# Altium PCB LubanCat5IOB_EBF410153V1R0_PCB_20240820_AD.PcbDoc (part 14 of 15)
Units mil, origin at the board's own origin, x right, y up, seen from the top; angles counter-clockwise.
Board outline 6811.02 x 4055.12 mil, 6 copper layers (TOP, GND02, ART03, ART04, PWR05, BOTTOM), stack 59.279 mil thick; 981 components, 783 nets, 3627 pads, 2669 vias.
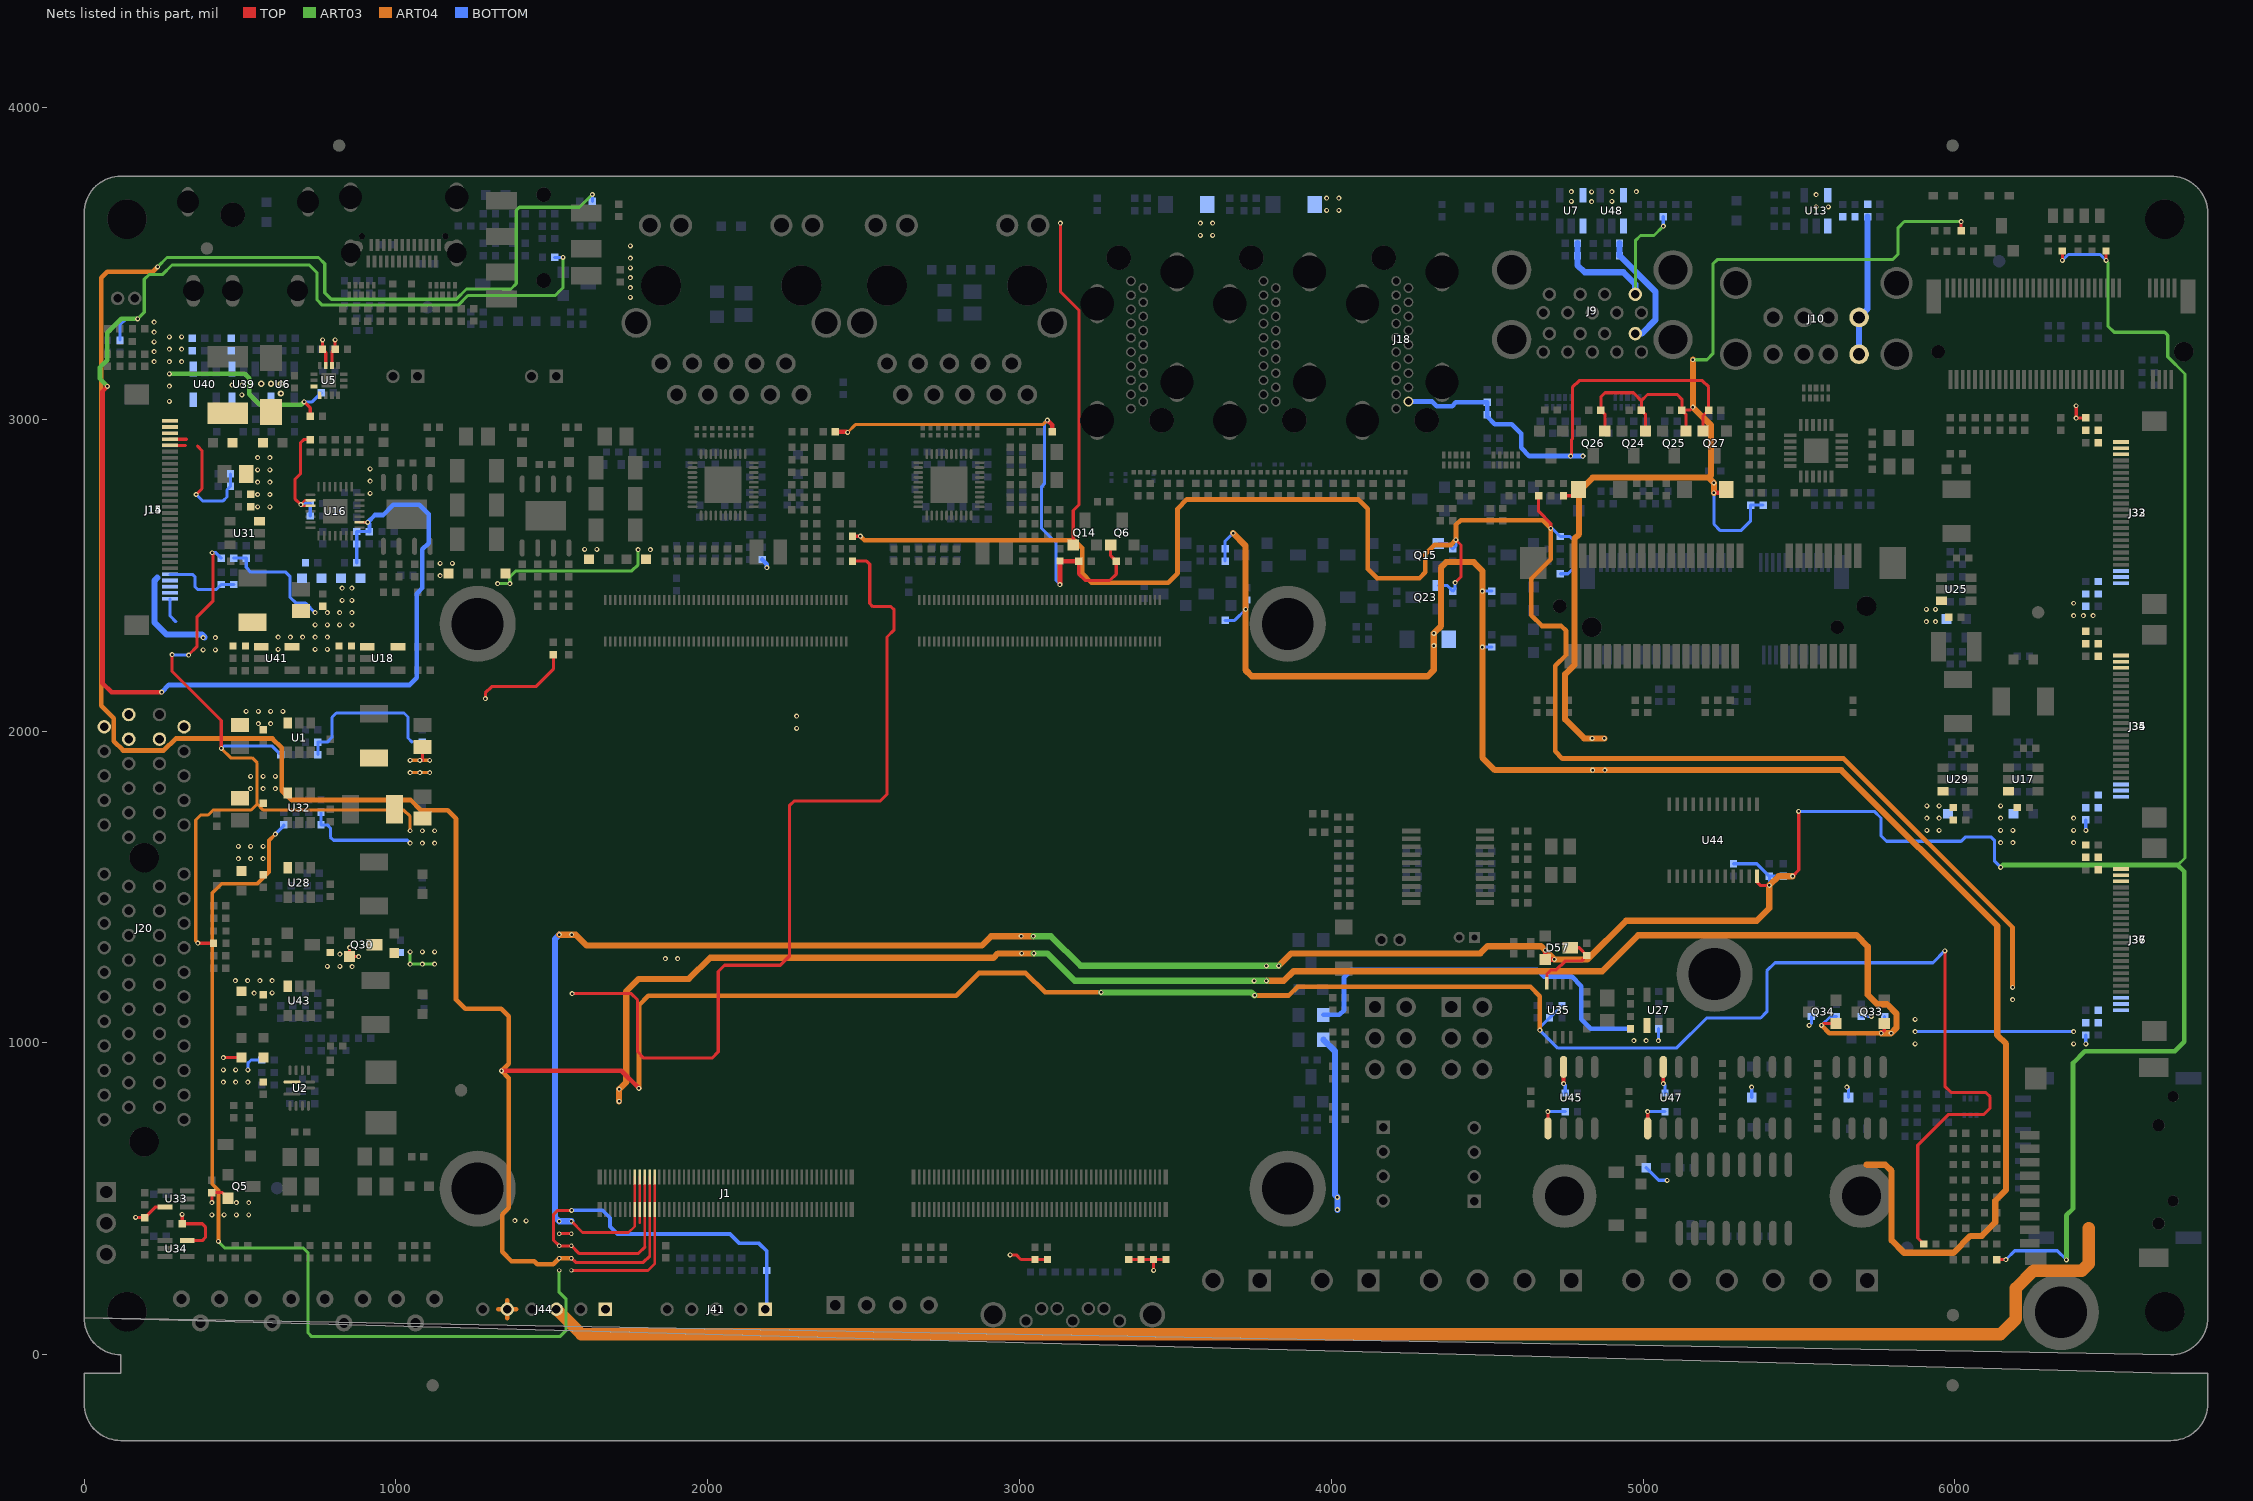
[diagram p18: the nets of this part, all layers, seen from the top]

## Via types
v1: diameter 16, hole 8, TOP to BOTTOM, 2357 vias
v2: diameter 14, hole 8, TOP to BOTTOM, 308 vias
v3: diameter 20, hole 10, TOP to BOTTOM, 4 vias

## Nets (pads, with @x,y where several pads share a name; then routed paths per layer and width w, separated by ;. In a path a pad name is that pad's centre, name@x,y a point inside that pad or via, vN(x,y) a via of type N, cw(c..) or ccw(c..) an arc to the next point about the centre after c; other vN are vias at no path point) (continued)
VCC5V0_HDMI_RX: C155.1 D40.2 D45.2 J18.18 Q27.2 R193.1 R213.1 | length 1577.4
  TOP w10: R193.1@4745,2754.69 4773.39,2754.69 D40.2@4793.07,2774.37 ; v1(4768,2882.16) 4771,2885.16 4771,2934.74 4773.5,2937.24 4773.5,3102.55 4795,3124.05 5190.32,3124.05 5210.32,3104.05 R213.1@5210.32,3029.37 5192.5,3011.55 Q27.2@5192.5,2962.87
  BOTTOM w15: J18.18@4247.48,3056.98 4323.94,3056.98 4338.74,3042.18 4387.81,3042.18 4400,3054.37 D45.2@4500.32,3054.37 C155.1@4500.32,3014.37 4500.32,3009.05 4525,2984.37 4579,2984.37 4609,2954.37 4609,2908.37 4635.21,2882.16 v1(4768,2882.16) v1(4807.37,2882.16)
VCC5V0_USB20_HOST: C285.1 C286.1 J9.10 U48.1 | length 376
  BOTTOM w20: C285.1@4924.68,3564.37 C286.1@4924.68,3524.37 5040,3409.05 5040,3319.37 4995.5,3274.86 J9.10@4975.24,3274.86
VCC5V0_USB20_HUB: C92.1 C97.1 C100.1 C101.1 J10.1 J10.7 U13.1 | length 452.1
  BOTTOM w20: J10.1@5692.92,3208.66 J10.7@5692.92,3326.77 5720.32,3354.17 C92.1@5720.32,3649.37
VCC5V0_USB30_OTG: C90.1 C91.1 J9.1 R150.1 U7.1 | length 624.4
  ART03 w10: J9.1@4975.24,3400.86 4975.24,3572.61 4992,3589.37 5035,3589.37 v1(5065,3619.37)
  BOTTOM w10: v1(5065,3619.37) R150.1@5065,3649.69
  BOTTOM w20: C90.1@4789.68,3564.37 C91.1@4789.68,3524.37 4789.68,3494.37 4812.68,3471.37 4937,3471.37 4975.24,3433.13 J9.1@4975.24,3400.86
VCC5V0_USB_S0: C7.2 C8.1 C11.1 C72.1 C73.1 L2.2 R4.2 U5.12 U5.13 U6.5 U7.5 U13.5 U48.5 | length 838.5
  TOP w10: v1(764.68,3254.68) C72.1@764.68,3225 775.16,3214.52 U5.13@775.16,3172.64 ; U5.12@794.84,3172.64 794.84,3214.52 C73.1@805.32,3225 v1(805.32,3254.68) ; v1@1085,1906.37 C8.1@1085,1949.33
  ART04 w10: v1(1045.63,1867) v1(1077.12,1867) v1(1108.61,1867) ; v1(1045.63,1906.37) v1(1077.12,1906.37) v1(1108.61,1906.37)
  BOTTOM w10: R4.2@749.68,1924.37 C7.2@749.68,1964.37 750,1964.69 779.69,1964.69 795,1980 795,2044 809.14,2058.14 1025.86,2058.14 1039,2045 1039,1977.69 1052,1964.69
  other v1: 224.37,3185.37 224.37,3216.86 224.37,3248.35 224.37,3279.84 224.37,3311.33 1752,3391.04 1752,3422.53 1752,3454.02 1752,3485.51 1752,3517 1752,3556.37 5555.03,3680.97 5594.4,3680.97 4835,3697.88 4770,3698.74 4900,3698.74 5555.03,3720.34 4835,3729.37 4770,3730.23 4900,3730.23 4978.74,3730.23
  other v3: 631.09,3082.51 568.11,3114 599.6,3114 631.09,3114
VCC12V_PCIEX4: C197.1 C198.1 J20.A2 J20.A3 J20.B1 J20.B2 J20.B3 Q30.3 | length 119.7
  ART03 w10: v1@1044.52,1293 v1(1045.63,1291.89) v1(1045.63,1252.52) v1(1085,1252.52) v1(1124.37,1252.52)
  other v1: 1085,1291.89 1124.37,1291.89
VCC_1V8_S0: J1.21 J1.22 Q15.1 Q23.1 Q33.1 Q34.1 R172.1 R174.1 R175.1 R191.1 R210.1 R273.2 R329.1 R332.1 R381.2 | length 15301.2
  TOP w8: 1829.63,291 J1.22@1829.63,465.62 J1.21@1829.63,569.96
  TOP w10: v2(1563.09,270.1) 1808.73,270.1 1829.63,291 ; R381.2@2464.68,2625 v1(2490,2625) ; v1(4397,2476) 4416,2495 4416,2597 v1(4400,2613) ; R210.1@4665,2754.69 4665,2705 4704,2666 v1(4704,2650) ; v1(5572.37,1056) 5578.24,1061.87 Q34.1@5618.5,1061.87 ; v1(5764,1030.87) 5773.5,1040.37 Q33.1@5773.5,1061.87
  ART03 w10: v1(431,363) 431,362 451,342 703,342 718,327 718,70 730,58 1526,58 1546,78 1546,178 1523.72,200.28 v2(1523.72,270.1)
  ART03 w20: v1(3046,1287) 3089,1287 3177,1199 v1(3752.63,1199) v1(3792,1199)
  ART04 w12: v1(431,363) 431,527 411,547 411,1481 440,1510 555,1510 593.23,1548.23 593.23,1649.37 v1(613.23,1669.37)
  ART04 w15: v1(2490,2625) 2503,2612 3176,2612 3201,2587 3201,2506 3231,2476 3477,2476 3507,2506 3507,2713 3537,2743 4087,2743 4117,2713 4117,2520 4147,2490 4283,2490 4302,2509 4302,2567 4332,2597 4384,2597 v1(4400,2613) 4400,2661.37 4415,2676.37 4677.63,2676.37 v1(4704,2650) 4704,2551 4641,2488 4641,2372.21 4676.21,2337 4738,2337 4753,2322 4753,2244 4718,2209 4718,1935 4741,1912 5644,1912 6185,1371 v1(6185,1178) ; v1(5572.37,1056) 5597.5,1030.87 v1(5764,1030.87)
  ART04 w20: v1(1716,812) v1(1716,851.37) 1739,874.37 1739,1165 1779,1205 1940,1205 2008,1273 2917,1273 2931,1287 v1(3006.63,1287) v1(3046,1287) ; v1(3792,1199) 3848,1199 3879,1230 4869,1230 4984,1345 5685,1345 5721,1309 5721,1154 5751,1124 5783,1124 5813,1094 5813,1048.38 v1(5795.49,1030.87) v1(5764,1030.87)
  BOTTOM w10: v1(613.23,1669.37) 640.32,1696.46 R273.2@640.32,1699.37 ; Q23.1@4343.5,2466.87 4372.18,2466.87 R191.1@4390,2449.05 4397,2456.05 v1(4397,2476) ; Q15.1@4343.5,2601.87 4372.18,2601.87 R172.1@4390,2584.05 4400,2594.05 v1(4400,2613) ; v1(4704,2650) 4709.05,2650 R174.1@4735,2624.05 4765.32,2624.05 4780,2609.37 4780,2525.33 4759.36,2504.69 R175.1@4735,2504.69 ; v1(5572.37,1056) 5601.06,1084.69 R332.1@5620,1084.69 ; v1(5764,1030.87) 5775,1041.87 R329.1@5775,1084.69
  other v1: 6185,1138.63
VCC_1V8_S3: J1.19 J1.20 R3.1 R119.1 R276.1 R284.1 | length 13845.3
  TOP w8: 1813.88,316 J1.20@1813.88,465.62 J1.19@1813.88,569.96
  TOP w10: v2(1563.09,309.47) 1576.56,296 1793.88,296 1813.88,316 ; R284.1@5900.32,355 5881,374.32 5881,672 5979,770 6092,770 6113.14,791.14 6113.14,826.86 6099,841 5988,841 5968,861 v1(5968,1295)
  TOP w15: v1(1338.74,910.37) 1723.35,910.37 v1(1779.71,854)
  ART03 w10: v1(236,3489) 266,3519 752,3519 772,3499 772,3406 793,3385 1193.54,3385 1226.54,3418 1369,3418 1386,3435 1386,3670 1396,3680 1589,3680 v1(1630,3721)
  ART03 w20: v1(3262,1162) 3744,1162 v1(3754,1152)
  ART04 w15: v1(236,3489) 220,3473 74,3473 55,3454 55,2081 95,2041 95,1968 125,1938 256,1938 294,1976 604,1976 634,1946 634,1809 664,1779 1047,1779 1080,1746 1166,1746 1193,1719 1193,1139 1223,1109 1338.13,1109 1362,1085.13 1362,933.63 v1(1338.74,910.37) 1362,887.11 1362,471 1340.79,449.79 1340.79,330 1370.79,300 1443.56,300 1453.59,289.97 1504.22,289.97 v2(1523.72,309.47) v2(1563.09,309.47) ; v1(1779.71,854) 1779.71,1121 1809.72,1151 2797,1151 2870,1224 3020,1224 3082,1162 v1(3262,1162) ; v1(3754,1152) 3864,1152 3892,1180 4639.05,1180 4669.05,1150 v1(4669.05,1040.95)
  BOTTOM w10: R119.1@1630,3699.05 v1(1630,3721) ; R3.1@4740,1119.68 4700.64,1080.32 R276.1@4700,1080.32 4669.05,1049.37 v1(4669.05,1040.95) 4727,983 5107,983 5204,1080 5377,1080 5397,1100 5397,1231 5423,1257 5930,1257 v1(5968,1295)
VCC_3V3_S0: C93.1 C216.1 C230.1 C231.1 C232.2 C313.1 D46.2 D49.2 J44.5 L21.2 L22.1 L23.1 L24.2 Q6.1 Q24.1 Q25.1 Q26.1 R6.2 R65.2 R100.1 R128.1 R151.1 R153.1 R154.1 R157.1 R158.1 R170.1 R178.1 R179.1 R196.1 R198.1 R199.1 R246.2 R272.2 R328.1 R330.1 R331.1 R356.1 R357.1 R358.1 R359.1 R360.1 R361.1 R363.2 R364.2 R382.2 R383.2 U45.5 U47.5 | length 15595
  TOP w10: v1(282,2245) 282,2192 440,2034 v1(440,1944.37) ; v1(335,2244) 362.57,2271.57 362.57,2366.57 414,2418 414,2569 v1(411,2572) ; v1(365.32,1319.69) R328.1@415,1319.69 ; v1(2970,320) 2990,320 3004.68,305.32 R360.1@3050,305.32 R361.1@3090,305.32 ; R170.1@3190.32,2545 3190.32,2503.32 3210.32,2483.32 3290.32,2483.32 3310.32,2503.32 R151.1@3310.32,2545 3292.5,2562.82 Q6.1@3292.5,2596.5 ; R358.1@3350,305.32 R359.1@3390,305.32 R356.1@3430,305.32 ; v1(3430,270) R356.1@3430,305.32 ; R357.1@3470,305.32 R356.1@3430,305.32 ; U45.5@4695,725.95 v1(4695,779.37) ; Q26.1@4877.5,2962.87 4877.5,3016.55 R199.1@4864.68,3029.37 4864.68,3071.68 4878,3085 4969.37,3085 4994.68,3059.69 ; Q24.1@5007.5,2962.87 5007.5,3016.55 R196.1@4994.68,3029.37 4994.68,3059.69 ; U47.5@5015,725.95 v1(5015,779.37) ; Q25.1@5137.5,2962.87 5137.5,3016.55 R198.1@5124.68,3029.37 ; v1(5160,3038.74) 5150.63,3029.37 R198.1@5124.68,3029.37 ; R128.1@6020.32,3604.37 v1(6020.32,3634.37) ; 4994.68,3059.69 5014.36,3079.37 5110,3079.37 5124.68,3064.69 R198.1@5124.68,3029.37
  TOP w15: R383.2@2409.68,2960 2446.41,2960 v1(2448.61,2957.8) ; v1(3089.28,2997.17) 3104.68,2981.77 R364.2@3104.68,2960 ; v1(3130,2470) R363.2@3130,2545.32 3130.32,2545 R170.1@3190.32,2545 ; v1(5227.37,2764.37) 5256.93,2764.37 D46.2@5266.93,2774.37
  ART03 w10: v1(5160,3191) 5205,3191 5224,3210 5224,3498 5238,3512 5800,3512 5818,3530 5818,3614.37 5838,3634.37 v1(6020.32,3634.37)
  ART04 w10: v1(365.32,1319.69) 358,1327.01 358,1715 374,1731 398.01,1731 414.01,1747 535.63,1747 555,1766.37 ; v1(440,1944.37) 470.37,1914 538.9,1914 555,1897.9 555,1766.37 ; v1(1045.63,1680.37) 1045.63,1726.37 1025.63,1746.37 575,1746.37 555,1766.37 ; v1(2448.61,2957.8) 2473.81,2983 3075.11,2983 v1(3089.28,2997.17)
  ART04 w15: J44.5@1328.63,145.66 J44.5@1357.28,145.66 ; J44.5@1357.28,117.01 J44.5@1357.28,145.66 ; J44.5@1357.28,174.32 J44.5@1357.28,145.66 ; J44.5@1385.94,145.66 J44.5@1357.28,145.66
  ART04 w20: v1(3685,2635) 3725,2595 v1(3725,2390) 3725,2196 3745,2176 4309,2176 4329,2196 v1(4329,2274.37) v1(4329,2313.74) 4352,2336.74 4352,2525 4369,2542 4456.72,2542 4485,2513.72 v1(4485,2449.05) v1(4485,2269.69) 4485,1915 4525,1875 v1(4838,1875) v1(4877.37,1875) 5636,1875 6136,1375 6136,1025 6164.28,996.72 6164.28,528.28 6130,494 6130,424 6087,381 6050,381 5996,327 5837,327 5797,367 5797,589 5777,609 5717,609 ; v1(4876.03,1976.62) v1(4836.66,1976.62) 4811.38,1976.62 4750,2038 4750,2182 4780,2212 4780,2617 4795,2632 4795,2769 4839,2813 5210.23,2813 ; v1(5160,3191) v1(5160,3038.74) 5218,2980.74 5218,2820.77 5210.23,2813 ; v1(5227.37,2764.37) v1(5227.37,2795.86) 5210.23,2813
  BOTTOM w10: v1(282,2245) 283,2244 v1(335,2244) ; v1(411,2572) 422.69,2572 R65.2@440,2554.69 ; v1(440,1944.37) 448.37,1952.74 601.95,1952.74 R6.2@630.32,1924.37 ; C232.2@759.68,1739.37 R272.2@759.68,1699.37 780,1699.37 790,1689.37 790,1660 800,1650 1036.63,1650 v1(1045.63,1641) ; v1(3089.28,2997.17) 3080,2987.89 3080,2793 3071,2784 3071,2650 3117,2604 3117,2483 v1(3130,2470) ; R157.1@3659.68,2355 3690,2355 v1(3725,2390) 3730,2395 R158.1@3730,2420.32 ; R154.1@3659.68,2545 R153.1@3659.68,2585 3659.68,2609.68 v1(3685,2635) ; v1(4485,2269.69) R179.1@4515,2269.69 ; v1(4485,2449.05) R178.1@4515,2449.05 ; v1(4695,779.37) C216.1@4750.32,779.37 ; v1(5015,779.37) C313.1@5070.32,779.37 ; v1(5049.43,1007.21) 5050,1007.78 R246.2@5050,1045.32 ; v1(5227.37,2764.37) 5227.37,2663.63 5248,2643 5313.63,2643 5345,2674.37 C93.1@5345,2724.69 R100.1@5385,2724.69 ; L23.1@5348.5,824.37 v1(5348.5,857.87) ; v1(5533,1056) 5540,1063 R331.1@5540,1084.69 ; v1(5653.5,857.87) 5658.5,852.87 L22.1@5658.5,824.37 ; R330.1@5700,1084.69 v1(5732.5,1084.69)
  BOTTOM w12: L24.2@5010.07,599.37 5050.07,559.37 v1(5077.2,559.37)
  BOTTOM w15: R382.2@2175,2550.32 2190,2535.32 v1(2190,2524)
  other v1: 1864.23,1270 1903.6,1270 1085,1641 1124.37,1641 1085,1680.37 1124.37,1680.37 2285,2008.74 2285,2048.11
VCC_3V3_S3: C81.1 C212.1 C213.1 C235.1 C236.1 D57.2 J1.13 J1.14 R87.1 R109.1 R111.2 R285.1 R353.1 U5.3 U5.4 U33.5 U34.5 U40.5 U41.5 U44.24 | length 12676.3
  TOP w8: 1746.63,392 1766.63,412 J1.14@1766.63,465.62 J1.13@1766.63,569.96
  TOP w10: v1(165,440.63) 165.95,439.68 C235.1@195,439.68 229.41,474.09 U33.5@259.57,474.09 ; v1(314.68,450) C236.1@314.68,420 379.09,420 389.09,410 389.09,375.91 379.09,365.91 U34.5@330.43,365.91 ; v1(706,3056) 725.32,3036.68 R87.1@725.32,3010 ; v2(1563.09,427.58) 1598.67,392 1746.63,392 ; U44.24@5365.75,1533.86 5365.75,1515 5375.75,1505 v1(5405,1505) ; v1(5479.69,1534.69) 5499.37,1554.37 v1(5499.37,1742.37) ; R285.1@6134.68,305 v1(6164,305) ; v1(6345,3509.37) R109.1@6345,3539.69 ; v1(6485,3509.37) R111.2@6485,3539.69
  TOP w15: v1(4686.5,1296.5) D57.2@4686.5,1267.5 v1(4715.5,1267.5)
  ART03 w10: v1(6485,3509.37) 6491,3503.37 6491,3299.37 6511,3279.37 6673,3279.37 6683,3269.37 6683,3200.37 6738,3145.37 6738,1593.12 6715.25,1570.37
  ART03 w15: v1(273.74,3146) 515,3146 530,3131 530,3081 564,3047 697,3047 v1(706,3056) ; v1(6146.85,1563.15) 6154.07,1570.37 6715.25,1570.37 6736,1549.62 6736,1003.37 6706,973.37 6417,973.37 6379,935.37 6379,468 6358,447 v1(6358,304.37)
  ART03 w20: v1(3045,1342) 3101,1342 3196,1247 v1(3791.63,1247) v1(3831,1247)
  ART04 w20: v1(1524,1347) v1(1563.37,1347) 1577,1347 1612,1312 2879,1312 2909,1342 v1(3005.63,1342) v1(3045,1342) ; v1(3831,1247) 3871,1287 4478,1287 4501,1310 4673,1310 v1(4686.5,1296.5) v1(4715.5,1267.5) 4821,1267.5 4945.5,1392 5365,1392 5405,1432 v1(5405,1505) 5434.69,1534.69 v1(5479.69,1534.69)
  BOTTOM w10: v1(706,3056) 731.32,3056 C81.1@760.32,3085 ; R353.1@5290,1574.68 5365.01,1574.68 C212.1@5405,1534.69 ; v1(5405,1505) C212.1@5405,1534.69 ; v1(5479.69,1534.69) C213.1@5450,1534.69 C212.1@5405,1534.69 ; v1(5499.37,1742.37) 5742,1742.37 5763,1721.37 5763,1664.37 5780.62,1646.75 6020.38,1646.75 6034.52,1660.89 6115.35,1660.89 6127.85,1648.39 6127.85,1582.15 v1(6146.85,1563.15) ; v1(6164,305) 6192.37,333.37 6329,333.37 v1(6358,304.37) ; v1(6345,3509.37) 6364,3528.37 6466,3528.37 v1(6485,3509.37)
  BOTTOM w20: v1(1524,1347) 1510,1333 1510,441.3 v2(1523.72,427.58) v2(1563.09,427.58)
  other v1: 1418,429 1382,430 622.52,2261.89 622.52,2301.26 661.89,2301.26 701.26,2301.26 273.74,3057.26 273.74,3106.63
VCC_5V0_S0: C184.1 C185.1 C217.1 C225.2 C226.1 C227.1 C314.1 D26.2 D33.2 J44.3 L20.2 Q14.1 R36.2 R127.1 R286.1 R311.1 R312.1 R313.1 R314.1 R315.1 R342.1 R348.1 U18.5 U27.1 U39.5 U45.3 U47.3 | length 8727.4
  TOP w10: v1(3131.14,3629) 3131.14,3409.86 3191,3350 3191,2726 3172.5,2707.5 Q14.1@3172.5,2596.5 ; v1(6389.3,3043.47) v1(6389.3,3004.1) 6389.88,3004.68 R286.1@6420,3004.68
  TOP w12: v1(4745,869.37) U45.3@4745,922.79 ; v1(5065,869.37) U47.3@5065,922.79
  ART04 w40: J44.3@1514.76,145.66 1594.92,65.5 6146.5,65.5 6196,115 6196,213 6252.57,269.57 6407.57,269.57 6430,292 6430,406
  BOTTOM w10: C225.2@480,2554.69 R36.2@520,2554.69 520,2525 535,2510 647,2510 660,2497 660,2430 680,2410 710.63,2410 v1(740.63,2380) ; v1(5065,869.37) 5070.32,864.05 C314.1@5070.32,839.37 ; v1(5873,1036.37) v1(6380.63,1036.37) ; v1(6420,997) R315.1@6420,1025.32 ; v1(6420,1681.26) R313.1@6420,1715.32
  BOTTOM w12: v1(4745,869.37) 4750.32,864.05 C217.1@4750.32,839.37
  BOTTOM w15: R127.1@3975,1090 4026,1090 4041,1105 4041,1211 4064.21,1234.21 4660.79,1234.21 4682,1213 4771,1213 4802,1182 4802,1075.32 4832,1045.32 C184.1@4960,1045.32
  other v1: 5873,997 6380.63,997 4970.69,1007.21 5010.06,1007.21 5873,1075.74 6380.63,1641.89 6380.63,1681.26 6380.63,1720.63 740.63,2340.63 780,2340.63 819.37,2340.63 858.74,2340.63 6380.63,2370.64 6412.12,2370.64 6443.61,2370.64 780,2380 819.37,2380 858.74,2380 6380.63,2410.01 1141.63,2498.61 1141.63,2537.98 1181,2537.98 1605.63,2582.98 1645,2582.98 506.09,3078.51 474.6,3110 506.09,3110 3580,3590 3619.37,3590 3580,3629.37 3619.37,3629.37 3985,3670 4024.37,3670 3985,3709.37 4024.37,3709.37
VCC_12V: C1.1 C2.1 C3.1 C12.1 C13.1 C17.1 C18.1 C19.1 C160.1 C161.1 C195.1 C196.1 C204.1 C205.1 C206.1 C228.1 C229.1 C233.1 C234.1 C249.1 C250.1 C293.1 C294.1 D1.2 F1.2 J44.1 Q5.2 Q30.2 R9.1 R131.1 R255.1 R319.1 R341.1 R347.1 U1.3 U2.1 U17.3 U25.3 U28.3 U29.3 U31.3 U32.3 U43.3 | length 1378.7
  TOP w10: v1(410,487.37) R319.1@410,519.69 443.68,519.69 Q5.2@461.5,501.87 ; v1(446.5,952.87) C17.1@505,952.87 ; v1(851.5,1305.87) Q30.2@851.5,1276.87 v1(880.5,1276.87)
  ART03 w10: v1(1326,2473.02) v1(1365.37,2473.02) 1365.37,2494 1385.37,2514 1757,2514 1777,2534 v1(1777,2582)
  BOTTOM w10: v1(525.24,913.5) 525.24,935.04 535.24,945.04 R9.1@570.32,945.04
  BOTTOM w20: R131.1@3975,1010 4012,973 4012,512.37 v1(4020,504.37) v1(4020,465)
  other v1: 410,448 449.37,448 488.74,448 528.11,448 488.74,487.37 528.11,487.37 446.5,874.13 485.87,874.13 525.24,874.13 446.5,913.5 485.87,913.5 545,1159.37 603.11,1160.63 485,1200 524.37,1200 563.74,1200 603.11,1200 780.63,1245.32 820,1245.32 859.37,1244.87 820,1284.69 495.12,1590.63 534.49,1590.63 573.86,1590.63 495.12,1630 534.49,1630 573.86,1630 6146.85,1641.89 6186.22,1641.89 5910.63,1681.26 5949.75,1681.26 6146.85,1681.26 6186.22,1681.26 5910.63,1720.63 5950,1720.63 6146.85,1720.63 5910.63,1760 5950,1760 6146.85,1760 534.49,1815.63 573.86,1815.63 613.23,1815.63 534.49,1855 573.86,1855 613.23,1855 559.05,2023.94 598.42,2023.94 519.68,2063.31 559.05,2063.31 598.42,2063.31 637.79,2063.31 5908.63,2351 5938,2351 5908.63,2390.37 5938,2390.37 1816.37,2582 556.22,2719.43 595.59,2719.43 556.22,2758.8 595.59,2758.8 917.57,2762.09 556.22,2798.17 595.59,2798.17 917.57,2801.46 556.22,2837.54 595.59,2837.54 917.57,2840.83 556.22,2876.91 595.59,2876.91
VCC_RTC: C237.1 D57.3 U35.8 | length 245.5
  TOP w10: U35.8@4691.61,1191.61 4691.61,1220.11 4705.5,1234 4722,1234 4750,1262 4801.68,1262 C237.1@4820,1280.32 4795.32,1305 D57.3@4766.5,1305
VCCA1V8_CODEC: C108.1 C114.1 C123.1 L14.2 R121.1 U16.2 U16.3 | length 390.1
  TOP w8: U16.3@726.26,2722.72 698.93,2722.72 v1(695,2726.65) 708.78,2740.43 U16.2@726.26,2740.43
  TOP w10: v1(695,2726.65) 676,2745.65 676,2807 694,2825 694,2924.68 704,2934.68 R121.1@725,2934.68
  BOTTOM w10: v1(695,2726.65) 698.35,2730 C108.1@725.32,2730 C114.1@725.32,2690
VCCA3V3_CODEC: C109.1 C110.1 C124.1 L15.2 R112.2 R113.2 R125.1 U16.16 | length 5138
  TOP w7: U16.16@883.74,2669.57 v1(909.57,2669.57)
  TOP w15: v1(75,3105.63) 59,3089.63 59,2154 88,2125 v1(249,2125)
  ART03 w10: v1(172,3322.37) 193,3343.37 193,3449 208,3464 251,3464 282,3495 722,3495 747,3470 747,3383 764,3366 1200,3366 1231,3397 1511.63,3397 1536,3421.37 v1(1536,3519.37)
  ART03 w15: v1(75,3105.63) 51,3129.63 51,3167 74,3190 74,3277 119.37,3322.37 v1(172,3322.37)
  BOTTOM w10: R125.1@115,3254.05 115,3302.37 135,3322.37 v1(172,3322.37) ; C124.1@874.68,2540 C109.1@874.68,2600 C110.1@874.68,2640 875,2639.68 R112.2@915,2639.68 ; R113.2@1509.68,3519.37 v1(1536,3519.37)
  BOTTOM w12: v1(909.57,2669.57) 915,2664.14 R112.2@915,2639.68
  BOTTOM w15: v1(249,2125) 272,2148 1044,2148 1067,2171 1067,2441 1085,2459 1085,2583 1105,2603 1105,2696 1075,2726 992,2726 959,2693 933,2693 v1(909.57,2669.57)
VCCA_1V8_S0: D24.1 J1.17 J1.18 J41.1 L14.1 R336.1 | length 1889.8
  TOP w8: 1798.13,345 J1.18@1798.13,465.62 J1.17@1798.13,569.96
  TOP w10: v1(1287,2104) 1287,2122.42 1307,2142.42 1448.66,2142.42 1505,2198.76 R336.1@1505,2245.32 ; v1(1564,463) 1519,463 1505,449 1505,367.56 v2(1523.72,348.84) v2(1563.09,348.84) 1586.93,325 1778.13,325 1798.13,345
  BOTTOM w12: v1(1564,463) 1663,463 1687,439 1687,411 1711,387 2072,387 2102,357 2165,357 2189.68,332.32 D24.1@2189.68,270 2189.68,150.66 J41.1@2184.68,145.66
  other v1: 827.25,2419.37 858.74,2419.37
VCCA_3V3_S0: J1.15 J1.16 L15.1 R77.1 | length 3037
  TOP w8: 1782.38,423.62 J1.16@1782.38,465.62 J1.15@1782.38,569.96
  TOP w10: v2(1523.72,388.21) v2(1563.09,388.21) ; v1(1565,1158) 1755,1158 1775,1138 1775,971 1795,951 2014,951 2034,971 2034,1229 2054,1249 2233,1249 2262,1278 2262,1760.87 2277.13,1776 2554,1776 2575,1797 2575,2302 2598,2325 2598,2389 2588,2399 2530,2399 2520,2409 2520,2535 2510,2545 R77.1@2464.68,2545
  other v1: 827.25,2458.74 858.74,2458.74
VDD_CAM0_5V: C267.1 C268.1 J32.1 J32.2 J32.3 R286.2
VDD_CAM1_5V: C266.1 C269.1 J33.1 J33.2 J33.3 R311.2
VDD_CAM2_5V: C270.1 C271.1 J34.1 J34.2 J34.3 R312.2
VDD_CAM3_5V: C272.1 C273.1 J35.1 J35.2 J35.3 R313.2
VDD_CAM4_5V: C274.1 C275.1 J36.1 J36.2 J36.3 R314.2
VDD_CAM5_5V: C276.1 C277.1 J37.1 J37.2 J37.3 R315.2
VDD_LCD0_3V3: C260.1 C261.1 J14.4 J14.5 R301.1 R303.1 U40.1 | length 461.9
  TOP w10: J14.5@275.91,2916.28 325.28,2916.28 ; J14.4@275.91,2935.97 327.97,2935.97 ; v1(359.37,2758.8) 378.37,2777.8 378.37,2899.63 364,2914
  BOTTOM w10: v1(359.37,2758.8) 379.74,2738.43 445.98,2738.43 458.48,2750.93 458.48,2773.8 R301.1@469.68,2785 R303.1@469.68,2825
  other v1: 313.11,3185.37 313.11,3224.74 313.11,3264.11
VDD_LCD0_5V: C256.1 C257.1 J14.1 J14.2 J14.3 U39.1
  other v1: 273.74,3185.37 273.74,3224.74 273.74,3264.11
VDD_LCD1_3V3: C263.1 C264.1 J15.4 J15.5 R302.1 R304.1 U41.1 | length 577.2
  BOTTOM w10: J15.5@275.91,2502.69 347.31,2502.69 356,2494 356,2462 364,2454 423.68,2454 R302.1@440,2470.32 R304.1@480,2470.32
  BOTTOM w20: 235,2492 226,2483 226,2348 264,2310 377.56,2310 v1@386.3,2301.26
  other v1: 381.57,2260.16 420.94,2260.16 381.57,2299.53 420.94,2299.53
VDD_LCD1_5V: C254.1 C255.1 J15.1 J15.2 J15.3 U18.1 | length 80.4
  BOTTOM w10: J15.1@275.91,2423.95 275.91,2369.09 294,2351
  other v1: 740.63,2261.89 780,2261.89 740.63,2301.26 780,2301.26
pads on no net: J1.30 J2.14 J2.16 J4.4 J4.6 J4.16 J4.22 J4.24 J4.26 J4.28 J4.52 J5. J6. J7. J8. J9.14 J9.15 J9.17 J9.18 J11. J11.7 J11.8 J13. J13.6 J13.8 J13.9 J13.10 J13.11 J13.12 J13.13 J13.14 J13.15 J13.16 J13.17 J13.19 J13.20 J13.21 J13.22 J13.23 J13.32 J13.34 J13.36 J13.38 J13.40 J13.42 J13.44 J13.46 J13.48 J13.50 J13.54 J13.58 J13.59 J13.60 J13.61 J13.62 J13.64 J13.65 J13.66 J13.67 J13.68 J13.70 J13.71 J13.73 J14.14 J15.14 J16. J17. J18. J18.14 J19. J19.5 J19.6 J19.7 J19.8 J19.11 J19.13 J19.17 J19.19 J19.20 J19.22 J19.23 J19.24 J19.25 J19.26 J19.28 J19.30 J19.32 J19.34 J19.36 J19.40 J19.42 J19.44 J19.46 J19.48 J19.56 J19.58 J19.67 J19.68 J19.69 J20. J20.A5 J20.A6 J20.A7 J20.A8 J20.A19 J20.A25 J20.A26 J20.A29 J20.A30 J20.A32 J20.B5 J20.B6 J20.B9 J20.B23 J20.B24 J20.B27 J20.B28 J20.B30 J21. J21.4 J21.6 J23. J23.3 J23.5 J23.6 J23.16 J23.17 J23.19 J23.28 J23.30 J23.32 J23.42 J23.44 J23.45 J23.46 J23.47 J23.48 J23.49 J23.51 J24. J28.1 J29.1 J32.13 J32.14 J33.13 J33.14 J34.13 J34.14 J34.16 J34.17 J34.19 J34.20 J35.13 J35.14 J35.16 J35.17 J35.19 J35.20 J36.13 J36.14 J36.16 J36.17 J36.19 J36.20 J37.13 J37.14 J37.16 J37.17 J37.19 J37.20 MARK.1 SS1.1 SS2.1 SS3.1 SS4.1 U2.4 U14.2 U14.19 U14.21 U14.22 U14.23 U14.24 U16.9 U16.25 U30.3 U44.1

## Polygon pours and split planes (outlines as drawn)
GND on BOTTOM "BOTTOM-GND" (solid, pour order 34): 82 vertices, not listed, extent 6371,1752.37 6434,1811.37
GND on BOTTOM "BOTTOM-GND 1" (solid, pour order 51): 82 vertices, not listed, extent 545,3608.37 625,3665.37
VCCA1V8_CODEC on BOTTOM "BOTTOM-VCCA1V8_CODEC" (solid, pour order 154): 683,2473 683,2505 657,2531 657,2738 661,2742 737,2742 737,2626 722,2611 722,2477 718,2473 683,2473
GND on BOTTOM "BOTTOM-GND 2" (solid, pour order 41): 82 vertices, not listed, extent 2413,3104 2473,3171
GND on BOTTOM "BOTTOM-GND 3" (solid, pour order 264): 40 vertices, not listed, extent 608,2939 1765,3629
VCC_5V0_S0 on BOTTOM "BOTTOM-VCC_5V0_S0" (solid, pour order 61): 82 vertices, not listed, extent 460,3037 516,3127
GND on BOTTOM "BOTTOM-GND 4" (solid, pour order 240): 20,595.37 20,3516.37 78,3516.37 78,3440.37 55,3417.37 55,2071.37 81,2045.37 81,606.37 70,595.37 20,595.37
VCC5V0_USB_S0 on BOTTOM "BOTTOM-VCC5V0_USB_S0" (solid, pour order 63): 588,3040 588,3096 582,3102 564,3102 559,3107 559,3122 564,3127 636,3127 640,3123 640,3050 630,3040 588,3040
GND on BOTTOM "BOTTOM-GND 5" (solid, pour order 281): 74 vertices, not listed, extent 1530,892.37 6791.02,3759.53
VCC5V0_USB20_HUB on BOTTOM "BOTTOM-VCC5V0_USB20_HUB" (solid, pour order 69): 5580,3596.37 5580,3653.37 5588,3661.37 5701,3661.37 5708,3668.37 5708,3701.37 5732,3701.37 5732,3637.37 5608,3637.37 5604,3633.37 5604,3596.37 5580,3596.37
VCC5V0_USB_S0 on BOTTOM "BOTTOM-VCC5V0_USB_S0 1" (solid, pour order 65): 82 vertices, not listed, extent 4890,3689.37 4990,3744.37
N17139454 on BOTTOM "BOTTOM-N17139454" (solid, pour order 79): 3915,1352 3915,1286 3924,1277 3953,1277 3953,1227 3884,1227 3875,1236 3875,1353 3914,1353 3915,1352
HDMI0_5V on BOTTOM "BOTTOM-HDMI0_5V" (solid, pour order 142): 82 vertices, not listed, extent 3395,3579.37 3495,3724.37
GND on BOTTOM "BOTTOM-GND 6" (solid, pour order 218): 27 vertices, not listed, extent 1584,847 1931,2493
VCC5V0_USB20_HOST on BOTTOM "BOTTOM-VCC5V0_USB20_HOST" (solid, pour order 44): 4926,3644.37 4926,3590.37 4913,3577.37 4913,3513.37 4941,3513.37 4950,3522.37 4950,3644.37 4926,3644.37
GND on BOTTOM "BOTTOM-GND 7" (solid, pour order 197): 82 vertices, not listed, extent 4690,3485.37 4948,3671.37
1V05_AVDD_PHY0 on BOTTOM "BOTTOM-1V05_AVDD_PHY0" (solid, pour order 52): 82 vertices, not listed, extent 2727,2882 2835,2925
N17139392 on BOTTOM "BOTTOM-N17139392" (solid, pour order 174): 3956,1355 4175,1355 4186,1344 4186,1266 4170,1250 3990,1250 3975,1265 3975,1287 3955,1307 3955,1354 3956,1355
VDD_LCD1_3V3 on BOTTOM "BOTTOM-VDD_LCD1_3V3" (solid, pour order 13): 302,2509.37 227,2509.37 222,2504.37 222,2483.37 228,2477.37 302,2477.37 302,2509.37
GND on BOTTOM "BOTTOM-GND 8" (solid, pour order 201): 82 vertices, not listed, extent 6568,1090.37 6680,1563.37
GND on BOTTOM "BOTTOM-GND 9" (solid, pour order 259): 44 vertices, not listed, extent 6431,20 6791.02,903.37
VDD_LCD1_3V3 on BOTTOM "BOTTOM-VDD_LCD1_3V3 1" (solid, pour order 42): 82 vertices, not listed, extent 372,2252 438,2313
GND on BOTTOM "BOTTOM-GND 10" (solid, pour order 244): 3256,1587 3256,2268 3238,2286 3059,2286 3010,2286 2995,2271 2995,1894 3040,1849 3040,1592 3066,1566 3235,1566 3256,1587
VCC_5V0_S0 on BOTTOM "BOTTOM-VCC_5V0_S0 1" (solid, pour order 202): 6425,988 5870,988 5864,994 5864,1079 5871,1086 6382,1086 6390,1078 6390,1045 6397,1038 6432,1038 6432,995 6425,988
VCC_12V on BOTTOM "BOTTOM-VCC_12V" (solid, pour order 1): 4010,515 4010,454 4031,454 4031,515 4010,515
GND on BOTTOM "BOTTOM-GND 11" (solid, pour order 191): 82 vertices, not listed, extent 6573,1898.37 6680,2260.37
VCC_5V0_S0 on BOTTOM "BOTTOM-VCC_5V0_S0 2" (solid, pour order 113): 46 vertices, not listed, extent 3565,3581 3635,3724.37
GND on BOTTOM "BOTTOM-GND 12" (solid, pour order 125): 983,2588 983,2695 993,2705 1077,2705 1087,2695 1087,2598 1077,2588 983,2588
GND on BOTTOM "BOTTOM-GND 13" (solid, pour order 274): 58 vertices, not listed, extent 1479,317 2439,2414
HDMI1_5V on BOTTOM "BOTTOM-HDMI1_5V" (solid, pour order 136): 82 vertices, not listed, extent 3745,3579.37 3840,3724.37
GND on BOTTOM "BOTTOM-GND 14" (solid, pour order 231): 22 vertices, not listed, extent 2418,1080 2717,2518
GND on BOTTOM "BOTTOM-GND 15" (solid, pour order 186): 499,3139 499,3319 480,3338 450,3338 438,3350 438,3511 452,3525 554,3525 563,3516 563,3145 557,3139 499,3139
VCC5V0_USB_S0 on BOTTOM "BOTTOM-VCC5V0_USB_S0 2" (solid, pour order 46): 82 vertices, not listed, extent 5546,3672.37 5606,3744.37
VCC_3V3_S0 on BOTTOM "BOTTOM-VCC_3V3_S0" (solid, pour order 58): 82 vertices, not listed, extent 4321,2264.37 4403,2323.37
N16630071 on BOTTOM "BOTTOM-N16630071" (solid, pour order 12): 903,2589 967,2589 967,2652 943,2652 943,2618 937,2612 903,2612 903,2589
VCC_3V3_S3 on BOTTOM "BOTTOM-VCC_3V3_S3" (solid, pour order 118): 362,3040 236,3040 226,3050 226,3148 234,3156 285,3156 293,3148 293,3104 310,3087 362,3087 362,3040
GND on BOTTOM "BOTTOM-GND 16" (solid, pour order 14): 82 vertices, not listed, extent 4991,2615.37 5040,2669.37
GND on BOTTOM "BOTTOM-GND 17" (solid, pour order 74): 82 vertices, not listed, extent 1335,3698.37 1445,3754.37
VCC3V3_PCIEX4 on BOTTOM "BOTTOM-VCC3V3_PCIEX4" (solid, pour order 237): 41 vertices, not listed, extent 220,1292 1136,1765.37
VCC5V0_USB_S0 on BOTTOM "BOTTOM-VCC5V0_USB_S0 3" (solid, pour order 122): 82 vertices, not listed, extent 1035,1857.37 1133,1977.37
GND on BOTTOM "BOTTOM-GND 18" (solid, pour order 126): 82 vertices, not listed, extent 5540,3529.37 5645,3645.37
VCC5V0_USB_S0 on BOTTOM "BOTTOM-VCC5V0_USB_S0 4" (solid, pour order 53): 82 vertices, not listed, extent 4760,3689.37 4845,3744.37
VDD_CAM3_5V on BOTTOM "BOTTOM-VDD_CAM3_5V" (solid, pour order 119): 6559,1835 6454,1835 6448,1829 6448,1773 6441,1766 6409,1766 6409,1743 6550,1743 6559,1752 6559,1835
GND on BOTTOM "BOTTOM-GND 19" (solid, pour order 210): 26 vertices, not listed, extent 2892,1453 3003,2526
GND on BOTTOM "BOTTOM-GND 20" (solid, pour order 295): 238 vertices, not listed, extent 21,20 6547,2917
VDD_LCD1_5V on BOTTOM "BOTTOM-VDD_LCD1_5V" (solid, pour order 213): 22 vertices, not listed, extent 248,2181 788,2468
VDD_CAM1_5V on BOTTOM "BOTTOM-VDD_CAM1_5V" (solid, pour order 109): 6560,2520 6507,2520 6507,2503 6496,2492 6448,2492 6448,2457 6443,2452 6408,2452 6408,2427 6552,2427 6560,2435 6560,2520
GND on BOTTOM "BOTTOM-GND 21" (solid, pour order 20): 82 vertices, not listed, extent 1112,3457.37 1168,3515.37
VCC_3V3_S0 on BOTTOM "BOTTOM-VCC_3V3_S0 1" (solid, pour order 111): 82 vertices, not listed, extent 1035,1632.37 1134,1732.37
VDD_CAM5_5V on BOTTOM "BOTTOM-VDD_CAM5_5V" (solid, pour order 106): 6559,1150 6508,1150 6508,1126 6499,1117 6448,1117 6448,1083 6441,1076 6408,1076 6408,1053 6550,1053 6559,1062 6559,1150
GND on BOTTOM "BOTTOM-GND 22" (solid, pour order 135): 82 vertices, not listed, extent 6552,3052.37 6615,3269.37
VCC_12V on BOTTOM "BOTTOM-VCC_12V 1" (solid, pour order 96): 82 vertices, not listed, extent 5902,1672 5994,1768
MINIPCIE_3V3 on BOTTOM "BOTTOM-MINIPCIE_3V3" (solid, pour order 107): 5904,2320 5987,2320 5997,2310 5997,2203 5974,2203 5974,2218 5967,2225 5906,2225 5899,2232 5899,2315 5904,2320
VCC12V_PCIEX4 on BOTTOM "BOTTOM-VCC12V_PCIEX4" (solid, pour order 92): 82 vertices, not listed, extent 1000,1244.37 1135,1304.37
VCC_5V0_S0 on BOTTOM "BOTTOM-VCC_5V0_S0 3" (solid, pour order 90): 46 vertices, not listed, extent 3915,3658 4035,3724.37
GND on BOTTOM "BOTTOM-GND 23" (solid, pour order 27): 82 vertices, not listed, extent 1122,3600 1214,3637
VCC_5V0_S0 on BOTTOM "BOTTOM-VCC_5V0_S0 4" (solid, pour order 72): 82 vertices, not listed, extent 6372,1638 6435,1734
GND on BOTTOM "BOTTOM-GND 24" (solid, pour order 104): 82 vertices, not listed, extent 6018,1672.37 6119,1768.37
VCC_1V8_S0 on BOTTOM "BOTTOM-VCC_1V8_S0" (solid, pour order 180): 19 vertices, not listed, extent 5755,1022 6197,1187
GND on BOTTOM "BOTTOM-GND 25" (solid, pour order 188): 1963,2711 2148,2711 2148,2911 1963,2911 1963,2711
VDD_LCD0_5V on BOTTOM "BOTTOM-VDD_LCD0_5V" (solid, pour order 166): 18 vertices, not listed, extent 251,3139 486,3330
GND on BOTTOM "BOTTOM-GND 26" (solid, pour order 184): 39 vertices, not listed, extent 740,2524 889,2780
VCCA_3V3_S0 on BOTTOM "BOTTOM-VCCA_3V3_S0" (solid, pour order 11): 808,2506 808,2454 815,2447 862,2447 867,2452 867,2463 861,2469 844,2469 839,2474 839,2506 808,2506
VCC_3V3_S3 on BOTTOM "BOTTOM-VCC_3V3_S3 1" (solid, pour order 2): 82 vertices, not listed, extent 1515,1334 1575,1358
GND on BOTTOM "BOTTOM-GND 27" (solid, pour order 94): 302,2568.37 187,2568.37 179,2560.37 179,2459.37 186,2452.37 207,2452.37 213,2458.37 213,2507.37 222,2516.37 302,2516.37 302,2568.37
M2EKEY_3V3 on BOTTOM "BOTTOM-M2EKEY_3V3" (solid, pour order 70): 82 vertices, not listed, extent 6227,2214 6330,2271
N17139440 on BOTTOM "BOTTOM-N17139440" (solid, pour order 139): 3928,936 3928,976 3915,989 3915,1190 3871,1190 3862,1181 3862,945 3871,936 3928,936
GND on BOTTOM "BOTTOM-GND 28" (solid, pour order 161): 58 vertices, not listed, extent 348,3042 458,3276
GND on BOTTOM "BOTTOM-GND 29" (solid, pour order 81): 82 vertices, not listed, extent 6445,1634.37 6516,1734.37
SATA_5V0 on BOTTOM "BOTTOM-SATA_5V0" (solid, pour order 83): 82 vertices, not listed, extent 1040,1044.37 1140,1119.37
VCC_5V0_S0 on BOTTOM "BOTTOM-VCC_5V0_S0 5" (solid, pour order 50): 82 vertices, not listed, extent 4944,997 5018,1058
GND on BOTTOM "BOTTOM-GND 30" (solid, pour order 132): 82 vertices, not listed, extent 6218,1633.37 6317,1768.37
VCC_5V0_S0 on BOTTOM "BOTTOM-VCC_5V0_S0 6" (solid, pour order 36): 6376,2418.37 6428,2418.37 6432,2414.37 6432,2384.37 6438,2378.37 6446,2378.37 6451,2373.37 6451,2365.37 6448,2362.37 6375,2362.37 6371,2366.37 6371,2413.37 6376,2418.37
VCC_12V on BOTTOM "BOTTOM-VCC_12V 2" (solid, pour order 59): 46 vertices, not listed, extent 5900,2341.37 5989,2397.37
VCCA_1V8_S0 on BOTTOM "BOTTOM-VCCA_1V8_S0" (solid, pour order 71): 746,2506 746,2417 755,2408 860,2408 867,2415 867,2432 859,2440 784,2440 778,2446 778,2506 746,2506
N17141824 on BOTTOM "BOTTOM-N17141824" (solid, pour order 152): 82 vertices, not listed, extent 1482,2871 1637,2981
VCC_12V on BOTTOM "BOTTOM-VCC_12V 3" (solid, pour order 97): 82 vertices, not listed, extent 6139,1633 6205,1768
GND on BOTTOM "BOTTOM-GND 31" (solid, pour order 198): 4823,1057 4809,1071 4809,1217 4820,1228 4954,1228 4962,1236 4962,1251 4974,1263 5050,1263 5077,1236 5077,1180 5066,1180 5066,1060 5063,1057 4823,1057
SATA_12V on BOTTOM "BOTTOM-SATA_12V" (solid, pour order 225): 82 vertices, not listed, extent 440,43.37 1185,177.37
M2EKEY_3V3 on BOTTOM "BOTTOM-M2EKEY_3V3 1" (solid, pour order 47): 82 vertices, not listed, extent 5558,2213.37 5591,2347.37
VBUS5V0_TYPEC on BOTTOM "BOTTOM-VBUS5V0_TYPEC" (solid, pour order 171): 612,3138 612,3272 624,3284 624,3582 618,3588 575,3588 569,3582 569,3282 580,3271 580,3145 587,3138 612,3138
VCC3V3_PCIECLK on BOTTOM "BOTTOM-VCC3V3_PCIECLK" (solid, pour order 54): 82 vertices, not listed, extent 4946,1150 5018,1215
VCC5V0_USB30_OTG on BOTTOM "BOTTOM-VCC5V0_USB30_OTG" (solid, pour order 22): 4795,3643.37 4795,3598.37 4778,3581.37 4778,3512.37 4802,3512.37 4802,3579.37 4819,3596.37 4819,3643.37 4795,3643.37
GND on BOTTOM "BOTTOM-GND 32" (solid, pour order 62): 82 vertices, not listed, extent 6504,2897.37 6589,2957.37
MINIPCIE_3V3 on BOTTOM "BOTTOM-MINIPCIE_3V3 1" (solid, pour order 10): 82 vertices, not listed, extent 4942,2614.37 4986,2668.37
VCCA3V3_CODEC on BOTTOM "BOTTOM-VCCA3V3_CODEC" (solid, pour order 68): 871,2475 871,2508 863,2516 863,2652 927,2652 927,2628 891,2628 887,2624 887,2527 902,2512 902,2475 871,2475
GND on BOTTOM "BOTTOM-GND 33" (solid, pour order 194): 2686,2709 2686,2945 2696,2955 2867,2955 2874,2948 2874,2726 2857,2709 2686,2709
GND on BOTTOM "BOTTOM-GND 34" (solid, pour order 288): 103 vertices, not listed, extent 199,271 1325,2137
M2PCIE_3V3 on BOTTOM "BOTTOM-M2PCIE_3V3" (solid, pour order 117): 82 vertices, not listed, extent 6623,3072.37 6705,3207.37
VDD_LCD0_3V3 on BOTTOM "BOTTOM-VDD_LCD0_3V3" (solid, pour order 89): 304,3268 304,3146 311,3139 362,3139 362,3270 356,3276 312,3276 304,3268
M2EKEY_3V3 on BOTTOM "BOTTOM-M2EKEY_3V3 2" (solid, pour order 39): 4901,2274.37 4901,2209.37 4918,2192.37 4918,2177.37 4913,2172.37 4867,2172.37 4862,2177.37 4862,2205.37 4870,2213.37 4870,2274.37 4901,2274.37
GND on ART04 "ART04-GND" (solid, pour order 290): 33 vertices, not listed, extent 20,20 946,1921
GND on ART04 "ART04-GND 1" (solid, pour order 294): 3997,3537 6333,3537 6370,3500 6370,2421 6229,2280 5436,2280 5361,2355 5361,2721 5365,2725 5272,2818 4024,2818 3995,2847 3995,3535 3997,3537
VCC_5V0_S0 on ART04 "ART04-VCC_5V0_S0" (solid, pour order 233): 26 vertices, not listed, extent 4732,854 5886,1085
GND on ART04 "ART04-GND 2" (solid, pour order 253): 3425,1599 3593,1599 3604,1588 3604,383 3586,365 3438,365 3413,390 3413,1587 3425,1599
VCC_1V8_S0 on ART04 "ART04-VCC_1V8_S0" (solid, pour order 0): 80 vertices, not listed, extent 6175,1128 6195,1188
HDMI0_5V on ART04 "ART04-HDMI0_5V" (solid, pour order 223): 82 vertices, not listed, extent 3326,3038.37 3483,3646.37
VCC_3V3_S0 on ART04 "ART04-VCC_3V3_S0" (solid, pour order 292): 59 vertices, not listed, extent 954,90 5758.5,1703
VBUS5V0_TYPEC on ART04 "ART04-VBUS5V0_TYPEC" (solid, pour order 216): 557.82,3687.82 575,3705 1075,3705 1090,3690 1090,3560.37 1080,3550.37 647.37,3550.37 627,3530 570,3530 557.82,3542.18 557.82,3687.82
VCCA_3V3_S0 on ART04 "ART04-VCCA_3V3_S0" (solid, pour order 249): 47 vertices, not listed, extent 819,380 1594,2471
VCC_3V3_S3 on ART04 "ART04-VCC_3V3_S3" (solid, pour order 260): 44 vertices, not listed, extent 264,421 1437,3156
VCCA_1V8_S0 on ART04 "ART04-VCCA_1V8_S0" (solid, pour order 243): 50 vertices, not listed, extent 819,314 1580,2429
N17141731 on ART04 "ART04-N17141731" (solid, pour order 150): 82 vertices, not listed, extent 1036,2877 1198,2979
VCC_1V8_S0 on ART04 "ART04-VCC_1V8_S0 1" (solid, pour order 5): 82 vertices, not listed, extent 1703,800 1729,862
GND on ART04 "ART04-GND 3" (solid, pour order 238): 82 vertices, not listed, extent 2036,1616 2920,1769
GND on ART04 "ART04-GND 4" (solid, pour order 279): 18 vertices, not listed, extent 3321,1799 4302,2713
VCC_3V3_S0 on ART04 "ART04-VCC_3V3_S0 1" (solid, pour order 241): 23 vertices, not listed, extent 2176,1998 3142,2533
GND on ART04 "ART04-GND 5" (solid, pour order 246): 6157,20 6157,202 6415,202 6457,244 6457,398 6487,428 6731,428 6791.02,367.98 6791.02,118.11 6790.82,111.82 6699.2,20.2 6692.91,20 6157,20
M2EKEY_3V3 on ART04 "ART04-M2EKEY_3V3" (solid, pour order 257): 26 vertices, not listed, extent 4819,2168.37 6329,2768.37
VCC_1V8_S0 on ART04 "ART04-VCC_1V8_S0 2" (solid, pour order 7): 82 vertices, not listed, extent 3746,1186 3814,1212
HDMI1_5V on ART04 "ART04-HDMI1_5V" (solid, pour order 224): 82 vertices, not listed, extent 3748,3036.37 3906,3644.37
VCC5V0_USB_S0 on ART04 "ART04-VCC5V0_USB_S0" (solid, pour order 251): 22 vertices, not listed, extent 562,3073 1760,3566
VCC5V0_USB_S0 on ART04 "ART04-VCC5V0_USB_S0 1" (solid, pour order 268): 24 vertices, not listed, extent 70,1848 1117,3320
GND on ART04 "ART04-GND 6" (solid, pour order 277): 3680,1608 4177,1608 4213,1644 4514,1644 4531,1661 5534,1661 5564,1631 5564,1430 5531,1397 4913,1397 4771,1255 3681,1255 3680,1256 3680,1608
MINIPCIE_3V3 on ART04 "ART04-MINIPCIE_3V3" (solid, pour order 220): 4834,2159 4929,2159 4945,2175 4945,2661 4953,2669 5062,2669 5077,2654 5077,2078 5065,2066 4832,2066 4819,2079 4819,2144 4834,2159
GND on ART04 "ART04-GND 7" (solid, pour order 283): 3005,1158 1896,1158 1776,1038 1776,916 1706,846 1706,350 1719,337 2968,337 3005,374 3005,1158
VCC_5V0_S0 on ART04 "ART04-VCC_5V0_S0 1" (solid, pour order 293): 63 vertices, not listed, extent 374,375.37 6557,3739.37
GND on ART04 "ART04-GND 8" (solid, pour order 261): 4137,526 5608,526 5640,494 5640,309 5633,302 4140,302 4127,315 4127,516 4137,526
VCC_3V3_S3 on ART04 "ART04-VCC_3V3_S3 1" (solid, pour order 8): 82 vertices, not listed, extent 3777,1234 3843,1261
GND on ART04 "ART04-GND 9" (solid, pour order 267): 2205,2471 2205,1856 2883,1856 2883,2471 2205,2471
VCC_12V on ART04 "ART04-VCC_12V" (solid, pour order 284): 60 vertices, not listed, extent 1648,109.37 6428,2403.37
GND on ART04 "ART04-GND 10" (solid, pour order 280): 6597,265.37 6566,296.37 6566,3517.37 6592,3543.37 6791.02,3543.37 6791.02,265.37 6597,265.37
VCC_5V0_S0 on TOP "TOP-VCC_5V0_S0" (solid, pour order 19): 82 vertices, not listed, extent 6379,2992 6432,3051
VCC_12V on TOP "TOP-VCC_12V" (solid, pour order 138): 82 vertices, not listed, extent 6140,1632 6213,1823
N16612146 on TOP "TOP-N16612146" (solid, pour order 87): 18 vertices, not listed, extent 2115.59,2535 2178.59,2710
GND on TOP "TOP-GND" (solid, pour order 289): 38 vertices, not listed, extent 3556,101 5840,998
VDD_CAM0_5V on TOP "TOP-VDD_CAM0_5V" (solid, pour order 105): 6559,2882 6507,2882 6507,2909 6503,2913 6448,2913 6448,2947 6442,2953 6408,2953 6408,2977 6552,2977 6559,2970 6559,2882
N16890980 on TOP "TOP-N16890980" (solid, pour order 116): 580,2649 508,2649 498,2639 498,2533 498,2530 498,2471 505,2464 585,2464 585,2519 540,2519 535,2524 535,2618 538,2621 580,2621 580,2649
VCC12V_PCIEX4 on TOP "TOP-VCC12V_PCIEX4" (solid, pour order 145): 907,1332.37 907,1254.37 917,1244.37 1127,1244.37 1134,1251.37 1134,1297.37 1127,1304.37 965,1304.37 957,1312.37 957,1332.37 907,1332.37
GND on TOP "TOP-GND 1" (solid, pour order 147): 6449,2991 6565,2991 6579,3005 6579,3262 6569,3272 6562,3272 6548,3258 6548,3216 6549,3215 6549,3097 6513,3061 6466,3061 6449,3044 6449,2991
MINIPCIE_3V3 on TOP "TOP-MINIPCIE_3V3" (solid, pour order 164): 17 vertices, not listed, extent 5891,2143 6056,2332.37
N16843509 on TOP "TOP-N16843509" (solid, pour order 130): 5945,1832 6023,1832 6030,1839 6030,1989.37 6035,1994.37 6055,1994.37 6055,2049.37 5965,2049.37 5965,1994.37 5980,1994.37 5989,1985.37 5989,1864 5984,1859 5945,1859 5945,1832
GND on TOP "TOP-GND 2" (solid, pour order 153): 1121,3471 1121,3614 1134,3627 1214,3627 1233,3608 1233,3493 1195,3455 1137,3455 1121,3471
GND on TOP "TOP-GND 3" (solid, pour order 120): 82 vertices, not listed, extent 5901,1867.37 5982,2005.37
GND on TOP "TOP-GND 4" (solid, pour order 245): 26 vertices, not listed, extent 448,1489 1183,2121
GND on TOP "TOP-GND 5" (solid, pour order 254): 18 vertices, not listed, extent 4613,1957 5326,2541
GND on TOP "TOP-GND 6" (solid, pour order 227): 82 vertices, not listed, extent 123,271.37 458,572.37
GND on TOP "TOP-GND 7" (solid, pour order 169): 111 vertices, not listed, extent 4616,1480 4820,1691.37
VCC_3V3_S0 on TOP "TOP-VCC_3V3_S0" (solid, pour order 168): 968,1794.37 1023,1794.37 1023,1753.37 1034,1742.37 1124,1742.37 1132,1734.37 1132,1637.37 1128,1633.37 978,1633.37 968,1643.37 968,1794.37
VCC3V3_PCIEX4 on TOP "TOP-VCC3V3_PCIEX4" (solid, pour order 151): 885,1466.37 1045,1466.37 1053,1474.37 1053,1487.37 1059,1493.37 1127,1493.37 1133,1487.37 1133,1407.37 1128,1402.37 1040,1402.37 1030.37,1412 885,1412 885,1466.37
N16835425 on TOP "TOP-N16835425" (solid, pour order 158): 18 vertices, not listed, extent 676,1497.37 975,1607.37
1V05_PHY1 on TOP "TOP-1V05_PHY1" (solid, pour order 114): 2210,2536 2322,2536 2322,2609 2327,2614 2362,2614 2362,2637 2322,2637 2298,2637 2298,2624 2289,2615 2210,2615 2210,2536
VBUS5V0_TYPEC on TOP "TOP-VBUS5V0_TYPEC" (solid, pour order 80): 18 vertices, not listed, extent 972,3604 1087,3704
GND on TOP "TOP-GND 8" (solid, pour order 115): 82 vertices, not listed, extent 6207,2882.37 6271,3048.37
VDD_LCD1_5V on TOP "TOP-VDD_LCD1_5V" (solid, pour order 101): 932,2259 798,2259 789,2250 737,2250 731,2256 731,2305 737,2311 860,2311 889,2282 932,2282 932,2259
GND on TOP "TOP-GND 9" (solid, pour order 275): 60 vertices, not listed, extent 1305,1315 2276,2290
N16891644 on TOP "TOP-N16891644" (solid, pour order 165): 18 vertices, not listed, extent 676,1962.37 976,2083.37
M2EKEY_3V3 on TOP "TOP-M2EKEY_3V3" (solid, pour order 141): 6263,2051 6263,2201.37 6250,2214.37 6236,2214.37 6236,2264 6242,2270 6325,2270 6330,2265 6330,2220 6318,2208 6318,2051 6263,2051
VCC_3V3_S3 on TOP "TOP-VCC_3V3_S3" (solid, pour order 67): 1521,436 1573,436 1604,405 1749,405 1762,418 1762,434 1770,434 1770,405 1751,386 1592,386 1565,413 1520,413 1515,418 1515,430 1521,436
GND on TOP "TOP-GND 10" (solid, pour order 43): 82 vertices, not listed, extent 1093,2168 1162,2227
GND on TOP "TOP-GND 11" (solid, pour order 192): 82 vertices, not listed, extent 5999,2802.37 6165,3048.37
GND on TOP "TOP-GND 12" (solid, pour order 235): 2692,1725 2329,1725 2305,1701 2305,1282 2318,1269 2534,1269 2553,1288 2553,1642 2571,1660 2668,1660 2693,1660 2702,1669 2702,1715 2692,1725
MINIPCIE_3V3 on TOP "TOP-MINIPCIE_3V3 1" (solid, pour order 24): 5662,2087 5707,2087 5716,2096 5716,2140 5707,2149 5670,2149 5662,2141 5662,2087
SATA_5V0 on TOP "TOP-SATA_5V0" (solid, pour order 148): 890,1031.37 1127,1031.37 1136,1040.37 1136,1100.37 1128,1108.37 1027,1108.37 1020,1101.37 1020,1092.37 1013,1085.37 890,1085.37 890,1031.37
GND on TOP "TOP-GND 13" (solid, pour order 95): 2429,607 2429,753 2477,753 2477,720 2491,720 2491,607 2429,607
GND on TOP "TOP-GND 14" (solid, pour order 250): 38 vertices, not listed, extent 361,2150 1072,2941
MINIPCIE_3V3 on TOP "TOP-MINIPCIE_3V3 2" (solid, pour order 91): 82 vertices, not listed, extent 4921,2525.37 4977,2668.37
GND on TOP "TOP-GND 15" (solid, pour order 35): 82 vertices, not listed, extent 6375,2226.37 6435,2288.37
GND on TOP "TOP-GND 16" (solid, pour order 206): 82 vertices, not listed, extent 6572,1099.37 6692,1582.37
GND on TOP "TOP-GND 17" (solid, pour order 263): 38 vertices, not listed, extent 2163,609 3067,1492
VCC_5V0_S0 on TOP "TOP-VCC_5V0_S0 1" (solid, pour order 76): 6372,1725.37 6372,1631 6380,1623 6432,1623 6432,1725.37 6424.37,1733 6379.63,1733 6372,1725.37
VCC_3V3_S0 on TOP "TOP-VCC_3V3_S0 1" (solid, pour order 211): 24 vertices, not listed, extent 1849,1260 2339,2056
GND on TOP "TOP-GND 18" (solid, pour order 234): 4716,2738 5258,2738 5273,2723 5273,2541 5257,2525 4730,2525 4708,2547 4708,2659 4693,2674 4693,2767 4716,2767 4716,2738
GND on TOP "TOP-GND 19" (solid, pour order 199): 4380,1395 4380,1280 4835,1280 4835,1395 4380,1395
N17139392 on TOP "TOP-N17139392" (solid, pour order 128): 4180,1340 4180,1228 4166,1214 4012,1214 4012,1262 4114,1262 4131,1279 4131,1340 4142,1351 4169,1351 4180,1340
VCC_3V3_S3 on TOP "TOP-VCC_3V3_S3 1" (solid, pour order 64): 749,3111 705,3111 698,3104 698,3005 705,2998 737,2998 737,3061 742,3066 761,3066 761,3089 749,3089 749,3111
N16593695 on TOP "TOP-N16593695" (solid, pour order 177): 22 vertices, not listed, extent 686,825.37 1002,1002.37
VCC_12V on TOP "TOP-VCC_12V 1" (solid, pour order 82): 5989,2424.37 5989,2350 5982,2343 5896,2343 5890,2349 5890,2393 5896,2399 5934,2399 5940,2405 5940,2431.37 5982,2431.37 5989,2424.37
N16593687 on TOP "TOP-N16593687" (solid, pour order 6): 778,1002.37 778,932.37 802,932.37 802,1002.37 778,1002.37
N17141731 on TOP "TOP-N17141731" (solid, pour order 49): 82 vertices, not listed, extent 1040,2844 1073,2979
N17085599 on TOP "TOP-N17085599" (solid, pour order 163): 18 vertices, not listed, extent 676,1117.37 980,1228.37
GND on TOP "TOP-GND 20" (solid, pour order 196): 82 vertices, not listed, extent 5967,3191 6239,3366
GND on TOP "TOP-GND 21" (solid, pour order 18): 3446,490 3476,490 3476,385 3472,381 3461,381 3457,385 3457,408 3446,419 3446,490
GND on TOP "TOP-GND 22" (solid, pour order 262): 31 vertices, not listed, extent 973,638 2077,1383
VDD_LCD0_5V on TOP "TOP-VDD_LCD0_5V" (solid, pour order 175): 302,2950 302,3090 292,3100 292,3268 287,3273 227,3273 221,3267 221,2965 236,2950 302,2950
VCC_12V on TOP "TOP-VCC_12V 2" (solid, pour order 129): 482,1208.37 658,1208.37 666,1200.37 666,1150.37 658,1142.37 484,1142.37 476,1150.37 476,1202.37 482,1208.37
VCC_12V on TOP "TOP-VCC_12V 3" (solid, pour order 40): 82 vertices, not listed, extent 1768,2524 1828,2591
MINIPCIE_3V3 on TOP "TOP-MINIPCIE_3V3 3" (solid, pour order 55): 82 vertices, not listed, extent 4742,2085 4884,2118
GND on TOP "TOP-GND 23" (solid, pour order 272): 28 vertices, not listed, extent 48,277 1136,1214
GND on TOP "TOP-GND 24" (solid, pour order 29): 82 vertices, not listed, extent 6379,2908.37 6434,2972.37
GND on TOP "TOP-GND 25" (solid, pour order 144): 82 vertices, not listed, extent 5870,2473.37 5985,2601.37
M2PCIE_3V3 on TOP "TOP-M2PCIE_3V3" (solid, pour order 178): 6051,2805 6009,2805 5997,2817 5997,3075 6011,3089 6011,3159 5946,3159 5938,3151 5938,2766 5956,2748 6051,2748 6051,2805
12V_DC on TOP "TOP-12V_DC" (solid, pour order 195): 20 vertices, not listed, extent 282,3165 525,3463.37
GND on TOP "TOP-GND 26" (solid, pour order 37): 82 vertices, not listed, extent 6370,1539.37 6434,1599.37
GND on TOP "TOP-GND 27" (solid, pour order 99): 82 vertices, not listed, extent 6023,1674.37 6118,1769.37
GND on TOP "TOP-GND 28" (solid, pour order 266): 87 vertices, not listed, extent 4968,1902 5933,3396
VCC_5V0_S0 on TOP "TOP-VCC_5V0_S0 2" (solid, pour order 45): 82 vertices, not listed, extent 1130,2482 1193,2549
GND on TOP "TOP-GND 29" (solid, pour order 162): 82 vertices, not listed, extent 6062,1861.37 6199,2008.37
GND on TOP "TOP-GND 30" (solid, pour order 179): 6448,2308.37 6448,2534.37 6455,2541.37 6488,2541.37 6496,2533.37 6496,2505.37 6501,2500.37 6582,2500.37 6586,2496.37 6586,2317.37 6577,2308.37 6448,2308.37
VCCA_1V8_S0 on TOP "TOP-VCCA_1V8_S0" (solid, pour order 98): 1519,357 1565,357 1573,349 1766,349 1793,376 1793,434 1802,434 1802,342 1781,321 1582,321 1575,328 1519,328 1515,332 1515,353 1519,357
N17141824 on TOP "TOP-N17141824" (solid, pour order 183): 1624,2607 1624,2990 1630,2996 1699,2996 1700,2995 1700,2610 1700,2605 1700,2580 1713,2567 1755,2567 1755,2535 1667,2535 1667,2601 1661,2607 1624,2607
VCC_12V on TOP "TOP-VCC_12V 4" (solid, pour order 133): 487,1633.37 487,1536.37 658,1536.37 666,1544.37 666,1580.37 594,1580.37 583,1591.37 583,1632.37 576,1639.37 493,1639.37 487,1633.37
GND on TOP "TOP-GND 31" (solid, pour order 157): 82 vertices, not listed, extent 4366,2451 4460,2651
GND on TOP "TOP-GND 32" (solid, pour order 140): 82 vertices, not listed, extent 6216,1632.37 6316,1775.37
GND on TOP "TOP-GND 33" (solid, pour order 17): 82 vertices, not listed, extent 1629,2383 1679,2441
N16935613 on TOP "TOP-N16935613" (solid, pour order 170): 18 vertices, not listed, extent 6122,1831 6240,2141
VDD_CAM4_5V on TOP "TOP-VDD_CAM4_5V" (solid, pour order 103): 6559,1512 6508,1512 6508,1538 6503,1543 6448,1543 6448,1578 6442,1584 6408,1584 6408,1607 6548,1607 6559,1596 6559,1512
M2PCIE_3V3 on TOP "TOP-M2PCIE_3V3 1" (solid, pour order 159): 20 vertices, not listed, extent 6080,2883 6234,3159
VCC_3V3_S0 on TOP "TOP-VCC_3V3_S0 2" (solid, pour order 88): 82 vertices, not listed, extent 4825,1864 4889,1988
GND on TOP "TOP-GND 34" (solid, pour order 73): 82 vertices, not listed, extent 181,2457.37 245,2553.37
GND on TOP "TOP-GND 35" (solid, pour order 56): 82 vertices, not listed, extent 5968,3328.37 6005,3455.37
N16594691 on TOP "TOP-N16594691" (solid, pour order 9): 711,870.37 779.37,870.37 802,893 802,917.37 778,917.37 778,903 762.37,887.37 711,887.37 708,884.37 708,873.37 711,870.37
GND on TOP "TOP-GND 36" (solid, pour order 248): 256,20 256,201.37 277,222.37 417,222.37 440,199.37 440,72.37 466,46.37 5815,46.37 5839,70.37 5839,211.37 5848,220.37 5904,220.37 5904,20 256,20
MINIPCIE_3V3 on TOP "TOP-MINIPCIE_3V3 4" (solid, pour order 16): 82 vertices, not listed, extent 5129,2085 5217,2117
N16890968 on TOP "TOP-N16890968" (solid, pour order 15): 450,2612 450,2540 457,2533 482,2533 482,2580 486,2584 486,2612 450,2612
GND on TOP "TOP-GND 37" (solid, pour order 252): 20 vertices, not listed, extent 1610,3629.37 6608,3759.53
